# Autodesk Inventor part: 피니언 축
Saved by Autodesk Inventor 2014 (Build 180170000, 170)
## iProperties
Created: 2025-06
Part Number: 피니언 축
Material: 강철, 탄소
Document SubType Name: Modeling
Designer: dg
Density: 7.87 g/cm^3
Appearance: 반연마
Mass: 234.348 g
Surface Area: 86.1217 cm^2
Volume: 29.7774 cm^3
Author: jhkim
Creation Date: 2025-05-27
Sending System: Autodesk Inventor 2026
Preprocessor: ST-DEVELOPER v20.1
Author: dg
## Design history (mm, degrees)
node "피니언 축1"
node "솔리드1"
node "기준1"
